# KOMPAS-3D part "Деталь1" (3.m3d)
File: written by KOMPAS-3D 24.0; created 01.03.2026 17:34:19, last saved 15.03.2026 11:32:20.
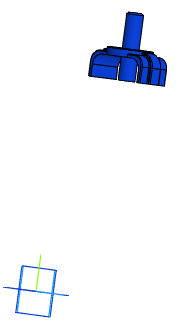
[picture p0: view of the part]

Document properties: Автор: R2D2; Полное имя файла: E:\Работа\Зайцев\GVWR2626M-2W-F-S Задвижка клиновая с выдвижным штоком DN.ru Ду50-300 Ру16\DN50\исходные материалы\3.m3d

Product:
- Body: Твердое тело1  | qty 1
    Масса: 0.395685
- Part/product: Деталь1
    Масса: 0.395685
    additional columns: Типовые

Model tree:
1. Твердое тело1  (labels: Твердое тело1)
2. Эскиз:1
3. Элемент выдавливания:1
     Расстояние 1 = 500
